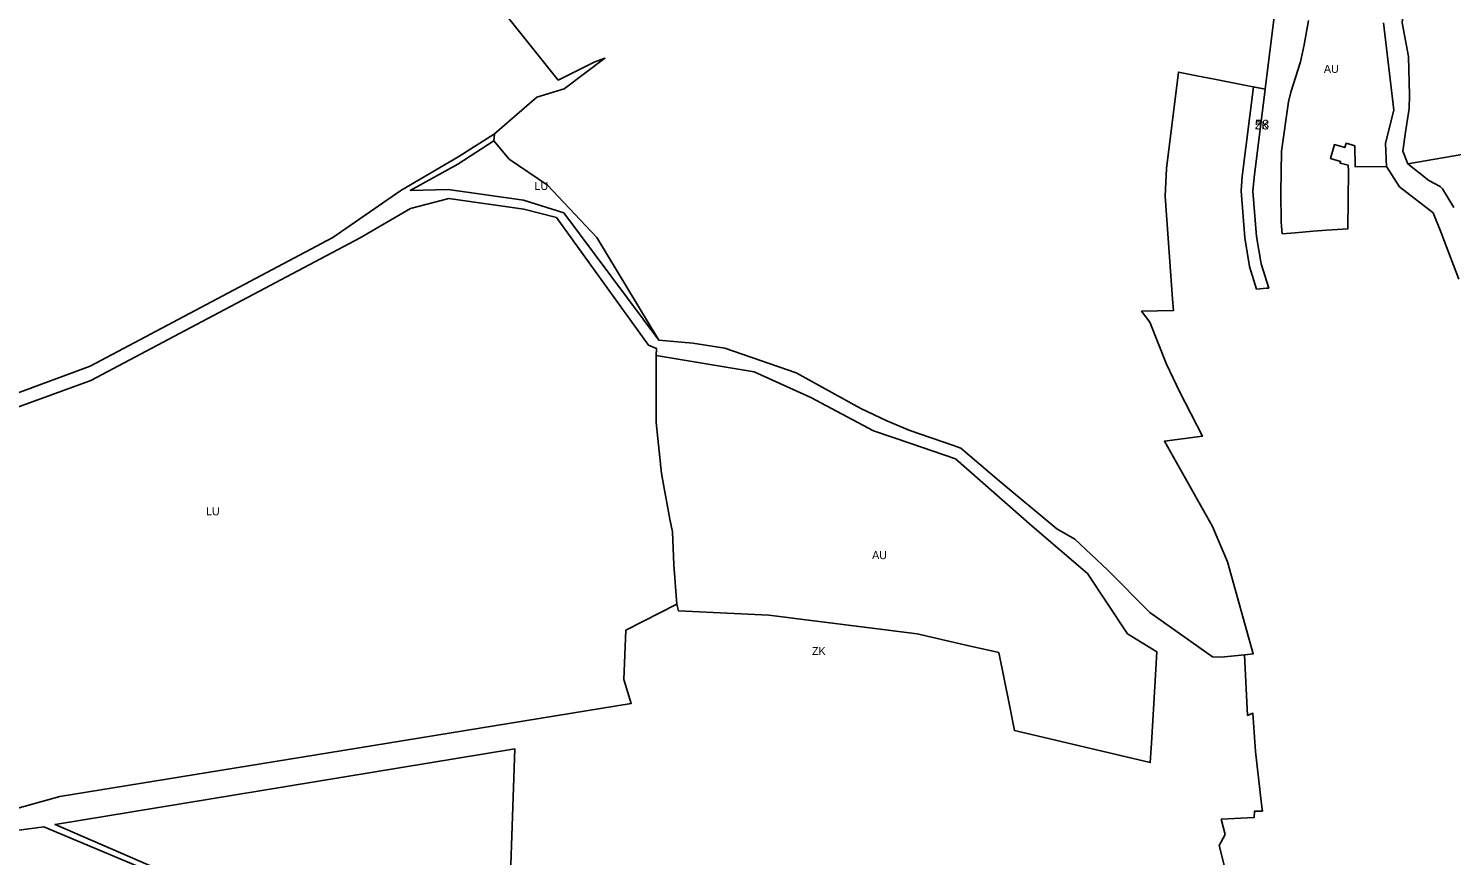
# Model space of a CAD drawing. Extents: x -521261 to -517465, y -1182764 to -1179456.
# Drawn here: x -520457 to -519568, y -1180873 to -1180356 of the extents above; entities that cross this region are included whole.
import ezdxf

# ---------------------------------------------------------------- set-up
doc = ezdxf.new("R2010")
doc.units = 0
for name, color, linetype in [('90640013', 7, 'Continuous'), ('90710013', 7, 'Continuous'), ('90710023', 7, 'Continuous'), ('90750013', 7, 'Continuous'), ('90770013', 7, 'Continuous'), ('ID_navrh', 7, 'Continuous')]:
    doc.layers.add(name, color=color, linetype=linetype)

msp = doc.modelspace()

# ---------------------------------------------------------------- linework, layer by layer
at = {"layer": '90640013'}
for points in [[(-519565.96, -1180328.26), (-519573.82, -1180328.67), (-519592.11, -1180322.38), (-519596.78, -1180324.51), (-519598.96, -1180350.54), (-519599.08, -1180352.83), (-519595.22, -1180373.94), (-519594.5, -1180398.05), (-519594.83, -1180406.45), (-519597.03, -1180421.15), (-519598.73, -1180433.05), (-519595.6, -1180440.97), (-519582.59, -1180451.31), (-519575.44, -1180455.06), (-519574.08, -1180456.6), (-519566.87, -1180468.21)], [(-519563.84, -1180512.91), (-519573.18, -1180488.44), (-519574.95, -1180483.48), (-519579.92, -1180471.63), (-519600.77, -1180455.29), (-519608.9, -1180442.55), (-519609.51, -1180428.04), (-519604.32, -1180407.52), (-519610.91, -1180352.92)]]:
    msp.add_lwpolyline(points, dxfattribs=at)
at = {"layer": '90710013'}
for points in [[(-520579.89, -1180626.79), (-520418.64, -1180567.25), (-520267.22, -1180487.01), (-520224.7, -1180457.68), (-520188.46, -1180436.35), (-520166.22, -1180422.25), (-520166.58, -1180426.67), (-520189.1, -1180441.12), (-520218.82, -1180457.68), (-520195.07, -1180457.1), (-520147.94, -1180463.58), (-520122.8, -1180471.55), (-520063.47, -1180551.19), (-520042.35, -1180553.05), (-520022.38, -1180556.11), (-519977.79, -1180571.45), (-519937.24, -1180593.79), (-519921.12, -1180601.42), (-519906.63, -1180607.48), (-519879.5, -1180616.96), (-519874.81, -1180618.65), (-519850.9, -1180639.04), (-519814.85, -1180668.94), (-519803.71, -1180675.31), (-519783.25, -1180694.48), (-519756.77, -1180721.21), (-519717.76, -1180748.91), (-519712.21, -1180749.16), (-519697.59, -1180747.55), (-519695.77, -1180785.42), (-519692.56, -1180784), (-519690.85, -1180807.9), (-519686.95, -1180840.95), (-519686.446, -1180845.217), (-519691.37, -1180845.18), (-519691.56, -1180849.19), (-519712.22, -1180850.29), (-519709.82, -1180859.87), (-519711.09, -1180862.2), (-519713.41, -1180866.64), (-519707.23, -1180891.41)], [(-520517.73, -1180858.28), (-520437.72, -1180836.09), (-520260.96, -1180807.27), (-520080.76, -1180777.95), (-520085.42, -1180763.05), (-520084.17, -1180732.28), (-520052.16, -1180715.87), (-520051.3, -1180720.05), (-519994.76, -1180722.85), (-519902.11, -1180734.59), (-519872.468, -1180741.326), (-519851.213, -1180746.156), (-519844.537, -1180778.953), (-519841.288, -1180794.911), (-519756.54, -1180814.92), (-519755.86, -1180802.82), (-519753.69, -1180767.33), (-519752.39, -1180745.68), (-519770.67, -1180734.47), (-519795.72, -1180696.92), (-519830.39, -1180667.29), (-519878.11, -1180625.31), (-519906.15, -1180615.63), (-519929.38, -1180607.81), (-519968.52, -1180586.94), (-520004.02, -1180570.89), (-520065.13, -1180560.74), (-520065.03, -1180556.21), (-520069.86, -1180554.25), (-520127.48, -1180474.4), (-520147.74, -1180469.38), (-520194.59, -1180462.72), (-520218.6, -1180468.97), (-520250.11, -1180487.13), (-520359.3, -1180545.16), (-520418.21, -1180576.2), (-520561.44, -1180628.41)], [(-520157.92, -1180932.93), (-520153.4, -1180806.35), (-520296.21, -1180829.93), (-520440.58, -1180853.57), (-520376.27, -1180881.41)], [(-520378.72, -1180883.92), (-520447.63, -1180855.08), (-520485.24, -1180860)]]:
    msp.add_lwpolyline(points, dxfattribs=at)
at = {"layer": '90710023'}
msp.add_lwpolyline([(-519699.038, -1180448.814), (-519692.103, -1180392.94), (-519684.8, -1180394.392), (-519691.65, -1180449.59), (-519692.37, -1180457.96), (-519690.13, -1180486.31), (-519687.23, -1180503.42), (-519682.557, -1180518.58), (-519683.897, -1180518.67), (-519690.126, -1180519.236), (-519694.471, -1180505.142), (-519697.508, -1180487.225), (-519699.822, -1180457.934)], close=True, dxfattribs=at)
at = {"layer": '90750013'}
for points in [[(-519675.24, -1180317.36), (-519684.8, -1180394.392), (-519697.727, -1180391.821), (-519701.937, -1180390.984), (-519715.469, -1180388.293), (-519728.401, -1180385.721), (-519738.869, -1180383.64), (-519746.341, -1180443.846), (-519747.26, -1180461.14), (-519742.58, -1180525.52), (-519741.98, -1180532.57), (-519762, -1180533.09), (-519756.87, -1180539.77), (-519746.34, -1180566.13), (-519737.99, -1180583.64), (-519734.67, -1180590.12), (-519723.97, -1180611.09), (-519747.7, -1180614.18), (-519717.59, -1180667.43), (-519708.21, -1180689.61), (-519692.2, -1180746.98), (-519697.59, -1180747.55), (-519712.21, -1180749.16), (-519717.76, -1180748.91), (-519756.77, -1180721.21), (-519783.25, -1180694.48), (-519803.71, -1180675.31), (-519814.85, -1180668.94), (-519850.9, -1180639.04), (-519874.81, -1180618.65), (-519879.5, -1180616.96), (-519906.63, -1180607.48), (-519921.12, -1180601.42), (-519937.24, -1180593.79), (-519977.79, -1180571.45), (-520022.38, -1180556.11), (-520042.35, -1180553.05), (-520063.47, -1180551.19), (-520102.14, -1180486.95), (-520132.98, -1180454.38), (-520157.02, -1180438.05), (-520166.58, -1180426.67), (-520166.22, -1180422.25), (-520139.65, -1180399.3), (-520122.61, -1180394.04), (-520097.16, -1180375.07), (-520103.92, -1180377.53), (-520126.31, -1180388.7), (-520163.84, -1180341.94)], [(-519543.828, -1180432.113), (-519595.6, -1180440.97), (-519598.73, -1180433.05), (-519597.03, -1180421.15), (-519594.83, -1180406.45), (-519594.5, -1180398.05), (-519595.22, -1180373.94), (-519599.08, -1180352.83), (-519598.96, -1180350.54), (-519596.78, -1180324.51), (-519592.11, -1180322.38), (-519573.82, -1180328.67), (-519565.96, -1180328.26)], [(-519610.91, -1180352.92), (-519604.32, -1180407.52), (-519609.51, -1180428.04), (-519608.9, -1180442.55), (-519628.633, -1180442.757), (-519628.633, -1180442.757), (-519628.77, -1180429.69), (-519630.58, -1180429.19), (-519634.228, -1180428.155), (-519635.01, -1180430.78), (-519641.53, -1180428.92), (-519643.95, -1180437.67), (-519637.6, -1180439.47), (-519637.935, -1180440.595), (-519632.85, -1180441.9), (-519632.79, -1180445.37), (-519633.03, -1180481.47), (-519646.47, -1180482.46), (-519654.73, -1180483.09), (-519666.04, -1180483.98), (-519674.05, -1180484.63), (-519674.81, -1180477.49), (-519674.98, -1180459.02), (-519674.65, -1180433.04), (-519670.2, -1180402.27), (-519668.67, -1180396.26), (-519662.6, -1180377.38), (-519660.39, -1180366.6), (-519657.79, -1180351.37)]]:
    msp.add_lwpolyline(points, dxfattribs=at)
msp.add_lwpolyline([(-519841.288, -1180794.911), (-519844.537, -1180778.953), (-519851.213, -1180746.156), (-519872.468, -1180741.326), (-519902.11, -1180734.59), (-519994.76, -1180722.85), (-520051.3, -1180720.05), (-520052.16, -1180715.87), (-520054.03, -1180691.48), (-520055.03, -1180670.89), (-520056.64, -1180662.89), (-520061.92, -1180634.28), (-520065.1, -1180602.48), (-520065.13, -1180560.74), (-520004.02, -1180570.89), (-519968.52, -1180586.94), (-519929.38, -1180607.81), (-519906.15, -1180615.63), (-519878.11, -1180625.31), (-519830.39, -1180667.29), (-519795.72, -1180696.92), (-519770.67, -1180734.47), (-519752.39, -1180745.68), (-519753.69, -1180767.33), (-519755.86, -1180802.82), (-519756.54, -1180814.92)], close=True, dxfattribs=at)
at = {"layer": '90770013'}
for points in [[(-520163.84, -1180341.94), (-520126.31, -1180388.7), (-520103.92, -1180377.53), (-520097.16, -1180375.07), (-520122.61, -1180394.04), (-520139.65, -1180399.3), (-520166.22, -1180422.25), (-520188.46, -1180436.35), (-520224.7, -1180457.68), (-520267.22, -1180487.01), (-520418.64, -1180567.25), (-520579.89, -1180626.79)], [(-520561.44, -1180628.41), (-520418.21, -1180576.2), (-520359.3, -1180545.16), (-520250.11, -1180487.13), (-520218.6, -1180468.97), (-520194.59, -1180462.72), (-520147.74, -1180469.38), (-520127.48, -1180474.4), (-520069.86, -1180554.25), (-520065.03, -1180556.21), (-520065.13, -1180560.74), (-520065.1, -1180602.48), (-520061.92, -1180634.28), (-520056.64, -1180662.89), (-520055.03, -1180670.89), (-520054.03, -1180691.48), (-520052.16, -1180715.87), (-520084.17, -1180732.28), (-520085.42, -1180763.05), (-520080.76, -1180777.95), (-520260.96, -1180807.27), (-520437.72, -1180836.09), (-520517.73, -1180858.28)], [(-520485.24, -1180860), (-520447.63, -1180855.08), (-520378.72, -1180883.92)]]:
    msp.add_lwpolyline(points, dxfattribs=at)
for points in [[(-520189.1, -1180441.12), (-520166.58, -1180426.67), (-520157.02, -1180438.05), (-520132.98, -1180454.38), (-520102.14, -1180486.95), (-520063.47, -1180551.19), (-520122.8, -1180471.55), (-520147.94, -1180463.58), (-520195.07, -1180457.1), (-520218.82, -1180457.68)], [(-520203.9, -1180952.83), (-520202.96, -1180943.49), (-520212.94, -1180946.42), (-520219.04, -1180948.87), (-520227.61, -1180952.85), (-520260.64, -1180952.48), (-520300.29, -1180947.88), (-520344.99, -1180950.96), (-520344.3, -1180943.96), (-520347.18, -1180922.08), (-520360, -1180918.29), (-520377.28, -1180904.27), (-520373.63, -1180892.94), (-520376.27, -1180881.41), (-520440.58, -1180853.57), (-520296.21, -1180829.93), (-520153.4, -1180806.35), (-520157.92, -1180932.93), (-520165.05, -1180947.64), (-520187.42, -1180954.15)]]:
    msp.add_lwpolyline(points, close=True, dxfattribs=at)

# ---------------------------------------------------------------- texts
at = {"layer": '90710013'}
msp.add_text('ZK', height=5, rotation=0, dxfattribs=at).set_placement((-519967.844, -1180747.745))
at = {"layer": '90710023'}
msp.add_text('ZK', height=5, rotation=0, dxfattribs=at).set_placement((-519691.19, -1180419.5))
at = {"layer": '90750013'}
for rotation, p in [(360, (-519648.085, -1180384.158)), (0, (-519930.282, -1180687.83))]:
    msp.add_text('AU', height=5, rotation=rotation, dxfattribs=at).set_placement(p)
at = {"layer": '90770013'}
for rotation, p in [(360, (-520141.145, -1180457.284)), (0, (-520346.37, -1180660.5))]:
    msp.add_text('LU', height=5, rotation=rotation, dxfattribs=at).set_placement(p)
at = {"layer": 'ID_navrh'}
msp.add_text('58', height=6, rotation=0, dxfattribs=at).set_placement((-519691.19, -1180419.5))

doc.saveas('drawing.dxf')
